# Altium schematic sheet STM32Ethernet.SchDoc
size A3
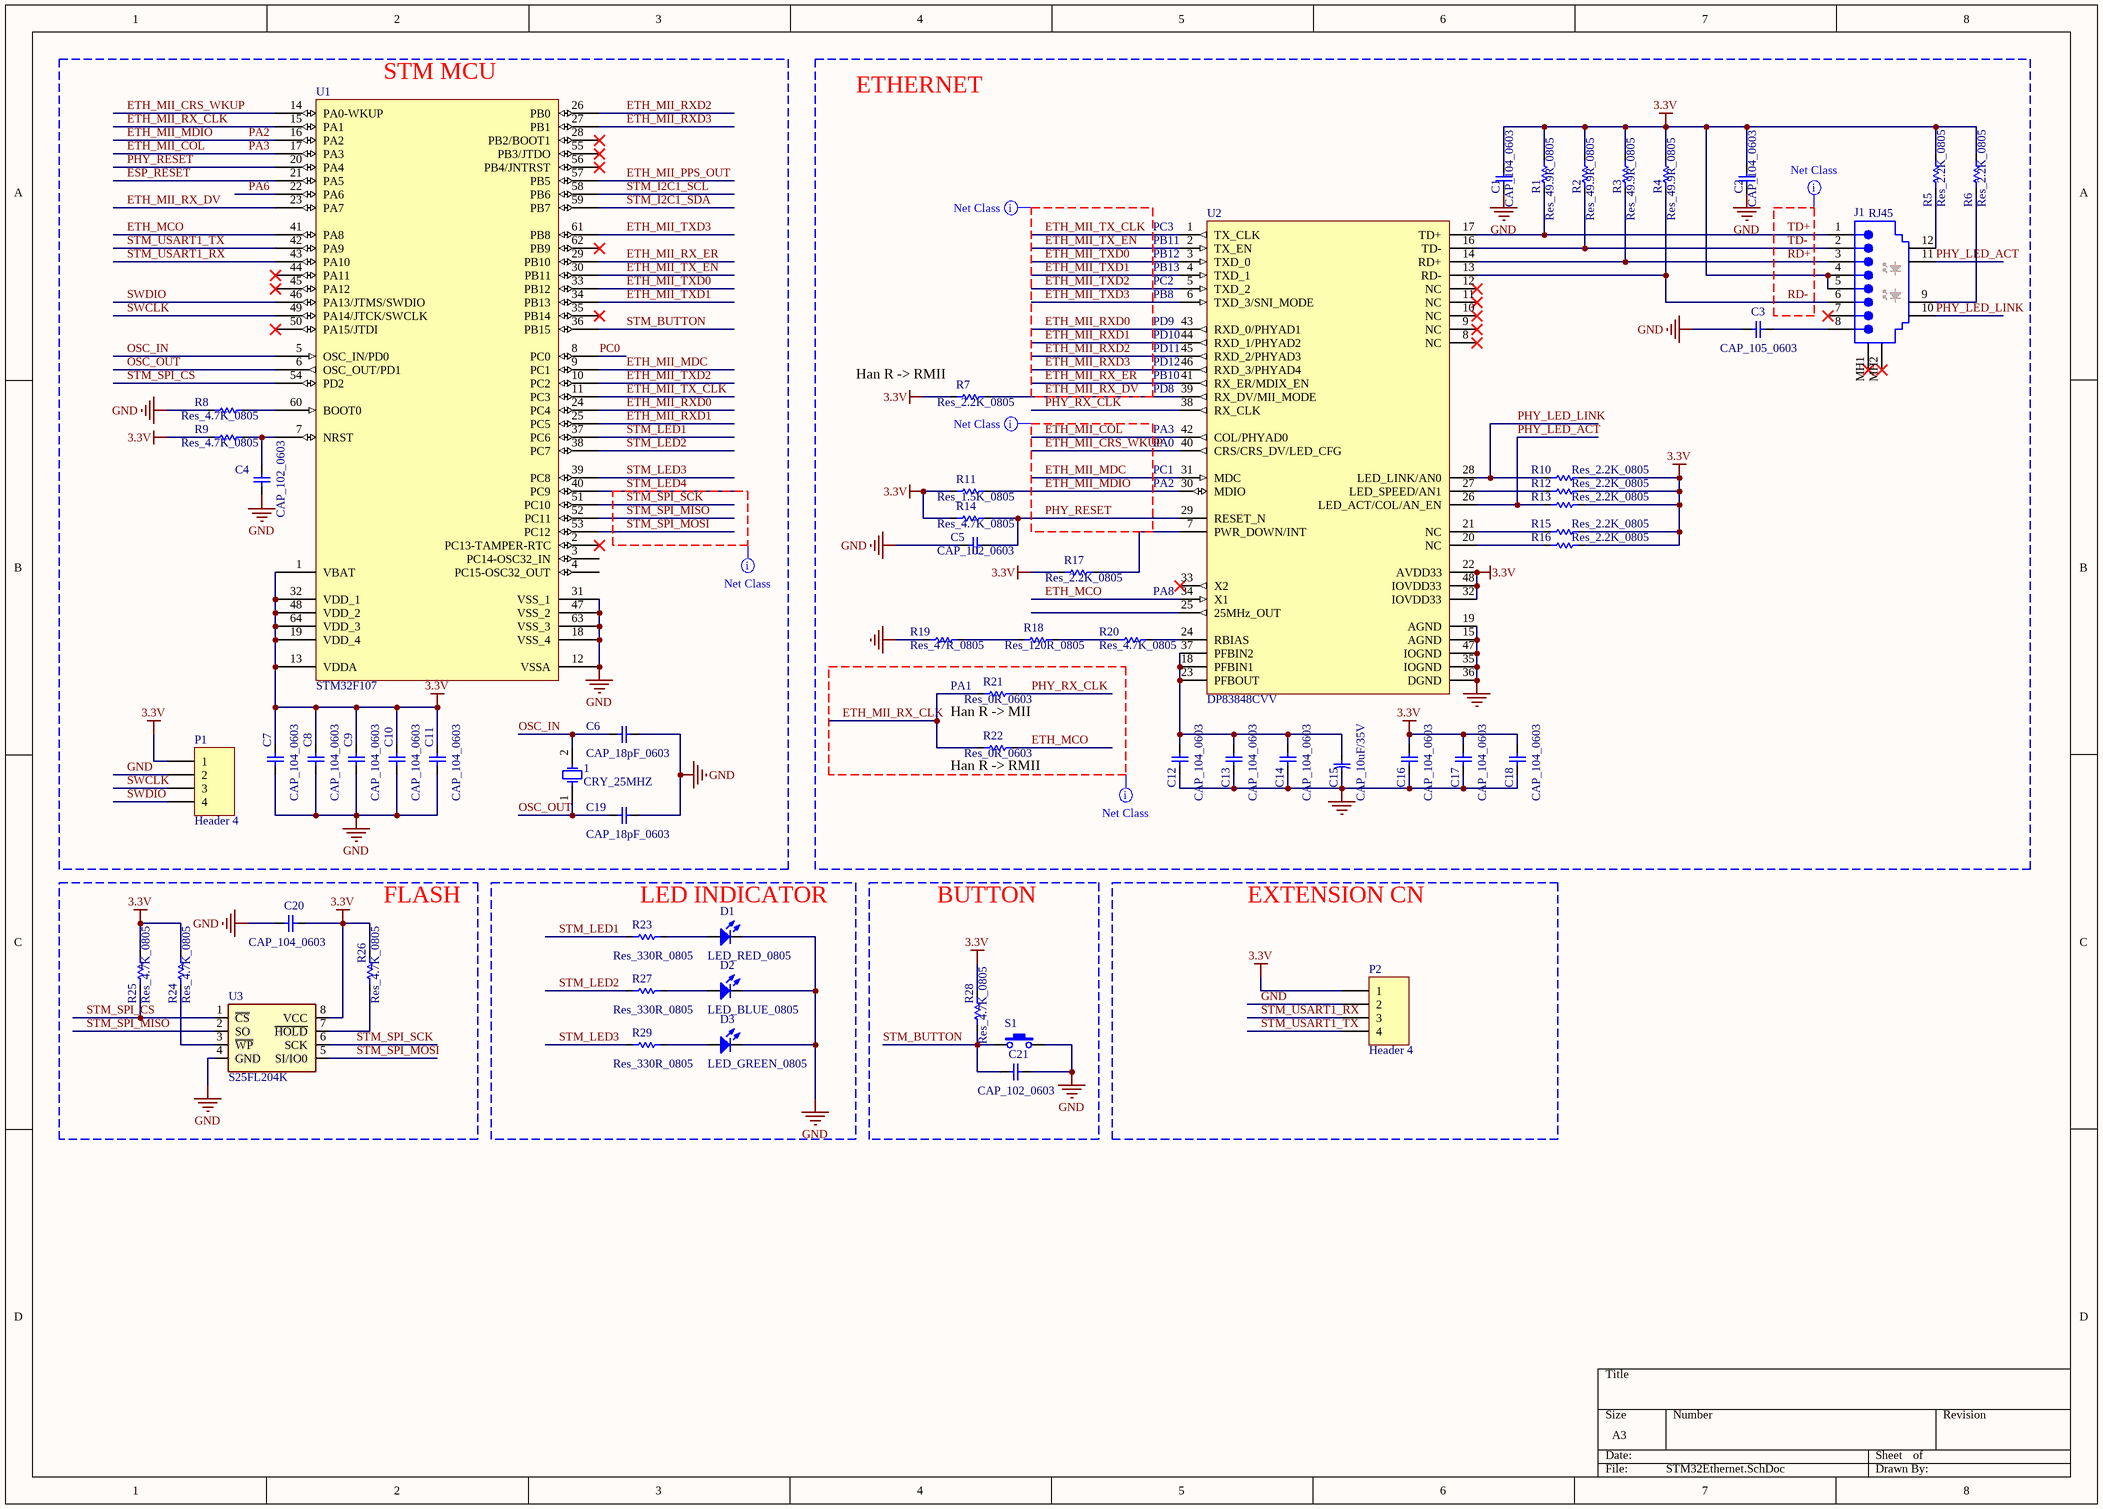
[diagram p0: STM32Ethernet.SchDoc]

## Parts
1  CRY_25MHZ  [cry]
C1  CAP_104_0603  [CAP_0805_TOP]
C2  CAP_104_0603  [CAP_0805_TOP]
C3  CAP_105_0603  [CAP_0805_TOP]
C4  CAP_102_0603  [CAP_0805_TOP]
C5  CAP_102_0603  [CAP_0805_TOP]
C6  CAP_18pF_0603  [CAP_0603_TOP]
C7  CAP_104_0603  [CAP_0805_TOP]
C8  CAP_104_0603  [CAP_0805_TOP]
C9  CAP_104_0603  [CAP_0805_TOP]
C10  CAP_104_0603  [CAP_0805_TOP]
C11  CAP_104_0603  [CAP_0805_TOP]
C12  CAP_104_0603  [CAP_0805_TOP]
C13  CAP_104_0603  [CAP_0805_TOP]
C14  CAP_104_0603  [CAP_0805_TOP]
C15  CAP_10uF/35V  [CAP_10uF/35V]
C16  CAP_104_0603  [CAP_0805_TOP]
C17  CAP_104_0603  [CAP_0805_TOP]
C18  CAP_104_0603  [CAP_0805_TOP]
C19  CAP_18pF_0603  [CAP_0603_TOP]
C20  CAP_104_0603  [CAP_0805_TOP]
C21  CAP_102_0603  [CAP_0805_TOP]
D1  LED_RED_0805  [LED 0805 TOP]
D2  LED_BLUE_0805  [LED 0805 TOP]
D3  LED_GREEN_0805  [LED 0805 TOP]
J1  RJ45  [CONNECTOR_RJ45_HR911102A]
P1  Header 4  [HDR1X4]
P2  Header 4  [HDR1X4]
R1  Res_49.9R_0805  [RES_0805_TOP]
R2  Res_49.9R_0805  [RES_0805_TOP]
R3  Res_49.9R_0805  [RES_0805_TOP]
R4  Res_49.9R_0805  [RES_0805_TOP]
R5  Res_2.2K_0805  [RES_0805_TOP]
R6  Res_2.2K_0805  [RES_0805_TOP]
R7  Res_2.2K_0805  [RES_0805_TOP]
R8  Res_4.7K_0805  [RES_0805_TOP]
R9  Res_4.7K_0805  [RES_0805_TOP]
R10  Res_2.2K_0805  [RES_0805_TOP]
R11  Res_1.5K_0805  [RES_0805_TOP]
R12  Res_2.2K_0805  [RES_0805_TOP]
R13  Res_2.2K_0805  [RES_0805_TOP]
R14  Res_4.7K_0805  [RES_0805_TOP]
R15  Res_2.2K_0805  [RES_0805_TOP]
R16  Res_2.2K_0805  [RES_0805_TOP]
R17  Res_2.2K_0805  [RES_0805_TOP]
R18  Res_120R_0805  [RES_0805_TOP]
R19  Res_47R_0805  [RES_0805_TOP]
R20  Res_4.7K_0805  [RES_0805_TOP]
R21  Res_0R_0603  [RES_0805_TOP]
R22  Res_0R_0603  [RES_0805_TOP]
R23  Res_330R_0805  [RES_0805_TOP]
R24  Res_4.7K_0805  [RES_0805_TOP]
R25  Res_4.7K_0805  [RES_0805_TOP]
R26  Res_4.7K_0805  [RES_0805_TOP]
R27  Res_330R_0805  [RES_0805_TOP]
R28  Res_4.7K_0805  [RES_0805_TOP]
R29  Res_330R_0805  [RES_0805_TOP]
S1  BUTTON 2P  [Nut nhan 2 chan  dung]  (value not drawn)
U1  STM32F107  [LQFP64_N]
U2  DP83848CVV  [LQFP48]
U3  S25FL204K  [SOIC_8]

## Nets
3.3V: C1.1 C2.1 C7.1 C8.1 C9.1 C10.1 C11.1 C16.2 C17.1 C18.2 C20.1 J1.4 J1.5 P1.1 P2.1 R1.1 R2.1 R3.1 R4.1 R5.1 R6.1 R7.2 R9.2 R10.1 R11.1 R12.1 R13.1 R14.1 R15.1 R16.1 R17.1 R24.1 R25.1 R26.1 R28.1 U1.1(VBAT) U1.13(VDDA) U1.19(VDD_4) U1.32(VDD_1) U1.48(VDD_2) U1.64(VDD_3) U2.22(AVDD33) U2.32(IOVDD33) U2.48(IOVDD33) U3.8(VCC)
GND: C1.2 C2.2 C3.1 C4.2 C5.1 C6.2 C7.2 C8.2 C9.2 C10.2 C11.2 C12.1 C13.1 C14.1 C15.2 C16.1 C17.2 C18.1 C19.2 C20.2 C21.2 D1.2(K) D2.2(K) D3.2(K) P1.2 P2.2 R8.2 R19.2 S1.2 U1.12(VSSA) U1.18(VSS_4) U1.31(VSS_1) U1.47(VSS_2) U1.63(VSS_3) U2.15(AGND) U2.19(AGND) U2.35(IOGND) U2.36(DGND) U2.47(IOGND) U3.4(GND)
ESP_RESET: U1.21(PA5)
ETH_MCO: R22.2 U1.41(PA8) U2.34(X1)
ETH_MII_COL: U1.17(PA3) U2.42(COL/PHYAD0)  [also labelled PA3]
ETH_MII_CRS_WKUP: U1.14(PA0-WKUP) U2.40(CRS/CRS_DV/LED_CFG)
ETH_MII_MDC: U1.9(PC1) U2.31(MDC)
ETH_MII_MDIO: R11.2 U1.16(PA2) U2.30(MDIO)  [also labelled PA2]
ETH_MII_PPS_OUT: U1.57(PB5)
ETH_MII_RX_CLK: R21.2 R22.1 U1.15(PA1)
ETH_MII_RX_DV: R7.1 U1.23(PA7) U2.39(RX_DV/MII_MODE)
ETH_MII_RX_ER: U1.29(PB10) U2.41(RX_ER/MDIX_EN)
ETH_MII_RXD0: U1.24(PC4) U2.43(RXD_0/PHYAD1)
ETH_MII_RXD1: U1.25(PC5) U2.44(RXD_1/PHYAD2)
ETH_MII_RXD2: U1.26(PB0) U2.45(RXD_2/PHYAD3)
ETH_MII_RXD3: U1.27(PB1) U2.46(RXD_3/PHYAD4)
ETH_MII_TX_CLK: U1.11(PC3) U2.1(TX_CLK)
ETH_MII_TX_EN: U1.30(PB11) U2.2(TX_EN)
ETH_MII_TXD0: U1.33(PB12) U2.3(TXD_0)
ETH_MII_TXD1: U1.34(PB13) U2.4(TXD_1)
ETH_MII_TXD2: U1.10(PC2) U2.5(TXD_2)
ETH_MII_TXD3: U1.61(PB8) U2.6(TXD_3/SNI_MODE)
OSC_IN: 1.2(OSC2) C6.1 U1.5(OSC_IN/PD0)
OSC_OUT: 1.1(OSC1) C19.1 U1.6(OSC_OUT/PD1)
PA6: U1.22(PA6)
PC0: U1.8(PC0)
PHY_LED_ACT: J1.11 R13.2 U2.26(LED_ACT/COL/AN_EN)
PHY_LED_LINK: J1.10 R10.2 U2.28(LED_LINK/AN0)
PHY_RESET: C5.2 R14.2 U1.20(PA4) U2.29(RESET_N)
PHY_RX_CLK: R21.1 U2.38(RX_CLK)
RD+: J1.3 R3.2 U2.14(RD+)
RD-: J1.6 R4.2 U2.13(RD-)
STM_BUTTON: C21.1 R28.2 S1.1 U1.36(PB15)
STM_I2C1_SCL: U1.58(PB6)
STM_I2C1_SDA: U1.59(PB7)
STM_LED1: R23.1 U1.37(PC6)
STM_LED2: R27.1 U1.38(PC7)
STM_LED3: R29.1 U1.39(PC8)
STM_LED4: U1.40(PC9)
STM_SPI_CS: R25.2 U1.54(PD2) U3.1(~{CS})
STM_SPI_MISO: U1.52(PC11) U3.2(SO)
STM_SPI_MOSI: U1.53(PC12) U3.5(SI/IO0)
STM_SPI_SCK: U1.51(PC10) U3.6(SCK)
STM_USART1_RX: P2.3 U1.43(PA10)
STM_USART1_TX: P2.4 U1.42(PA9)
SWCLK: P1.3 U1.49(PA14/JTCK/SWCLK)
SWDIO: P1.4 U1.46(PA13/JTMS/SWDIO)
TD+: J1.1 R1.2 U2.17(TD+)
TD-: J1.2 R2.2 U2.16(TD-)
NetC3_2: C3.2 J1.8
NetC4_1: C4.1 R9.1 U1.7(NRST)
NetC12_2: C12.2 C13.2 C14.2 C15.1 U2.18(PFBIN1) U2.23(PFBOUT) U2.37(PFBIN2)
NetD1_1: D1.1(A) R23.2
NetD2_1: D2.1(A) R27.2
NetD3_1: D3.1(A) R29.2
NetJ1_9: J1.9 R6.2
NetJ1_12: J1.12 R5.2
NetR8_1: R8.1 U1.60(BOOT0)
NetR12_2: R12.2 U2.27(LED_SPEED/AN1)
NetR15_2: R15.2 U2.21(NC)
NetR16_2: R16.2 U2.20(NC)
NetR17_2: R17.2 U2.7(PWR_DOWN/INT)
NetR18_1: R18.1 R19.1
NetR18_2: R18.2 R20.2
NetR20_1: R20.1 U2.24(RBIAS)
NetR24_2: R24.2 U3.3(~{WP})
NetR26_2: R26.2 U3.7(~{HOLD})

Not connected (* = marked no-connect by the designer): J1 7* MH1(Shield)* MH2(Shield)*; U1 2(PC13-TAMPER-RTC)* 3(PC14-OSC32_IN) 4(PC15-OSC32_OUT) 28(PB2/BOOT1)* 35(PB14)* 44(PA11)* 45(PA12)* 50(PA15/JTDI)* 55(PB3/JTDO)* 56(PB4/JNTRST)* 62(PB9)*; U2 8(NC)* 9(NC)* 10(NC)* 11(NC)* 12(NC)* 25(25MHz_OUT) 33(X2)*

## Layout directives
net class ETH_SIGN: 3.3V, ETH_MCO, ETH_MII_COL, ETH_MII_CRS_WKUP, ETH_MII_MDC, ETH_MII_MDIO, ETH_MII_RX_CLK, ETH_MII_RX_DV, ETH_MII_RX_ER, ETH_MII_RXD0, ETH_MII_RXD1, ETH_MII_RXD2, ETH_MII_RXD3, ETH_MII_TX_CLK, ETH_MII_TX_EN, ETH_MII_TXD0, ETH_MII_TXD1, ETH_MII_TXD2, ETH_MII_TXD3, GND, PHY_LED_ACT, PHY_LED_LINK, PHY_RESET, PHY_RX_CLK, RD+, RD-, TD+, TD-
net class ETH_CLK: 3.3V, ETH_MCO, ETH_MII_COL, ETH_MII_CRS_WKUP, ETH_MII_MDC, ETH_MII_MDIO, ETH_MII_RX_CLK, ETH_MII_RX_DV, ETH_MII_RX_ER, ETH_MII_RXD0, ETH_MII_RXD1, ETH_MII_RXD2, ETH_MII_RXD3, ETH_MII_TX_CLK, ETH_MII_TX_EN, ETH_MII_TXD0, ETH_MII_TXD1, ETH_MII_TXD2, ETH_MII_TXD3, GND, PHY_LED_ACT, PHY_LED_LINK, PHY_RESET, PHY_RX_CLK, RD+, RD-, TD+, TD-
net class PHY_OUT: 3.3V, ETH_MCO, ETH_MII_COL, ETH_MII_CRS_WKUP, ETH_MII_MDC, ETH_MII_MDIO, ETH_MII_RX_CLK, ETH_MII_RX_DV, ETH_MII_RX_ER, ETH_MII_RXD0, ETH_MII_RXD1, ETH_MII_RXD2, ETH_MII_RXD3, ETH_MII_TX_CLK, ETH_MII_TX_EN, ETH_MII_TXD0, ETH_MII_TXD1, ETH_MII_TXD2, ETH_MII_TXD3, GND, PHY_LED_ACT, PHY_LED_LINK, PHY_RESET, PHY_RX_CLK, RD+, RD-, TD+, TD-
net class SPI_DATA: 3.3V, ESP_RESET, ETH_MCO, ETH_MII_COL, ETH_MII_CRS_WKUP, ETH_MII_MDC, ETH_MII_MDIO, ETH_MII_PPS_OUT, ETH_MII_RX_CLK, ETH_MII_RX_DV, ETH_MII_RX_ER, ETH_MII_RXD0, ETH_MII_RXD1, ETH_MII_RXD2, ETH_MII_RXD3, ETH_MII_TX_CLK, ETH_MII_TX_EN, ETH_MII_TXD0, ETH_MII_TXD1, ETH_MII_TXD2, ETH_MII_TXD3, GND, OSC_IN, OSC_OUT, PA2, PA3, PA6, PC0, PHY_RESET, STM_BUTTON, STM_I2C1_SCL, STM_I2C1_SDA, STM_LED1, STM_LED2, STM_LED3, STM_LED4, STM_SPI_CS, STM_SPI_MISO, STM_SPI_MOSI, STM_SPI_SCK, STM_USART1_RX, STM_USART1_TX, SWCLK, SWDIO

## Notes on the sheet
- (near U1) STM MCU
- ETHERNET
- (near U2) PC3
- (near U2) PB11
- (near U2) PB12
- (near U2) PB13
- (near U2) PC2
- (near U2) PB8
- (near R7) Han R -> RMII
- (near U2) PD9
- (near U2) PD10
- (near U2) PD11
- (near U2) PD12
- (near U2) PB10
- (near U2) PD8
- (near U2) PA3
- (near U2) PA0
- (near U2) PC1
- (near U2) PA2
- PA8
- (near R21) PA1
- (near R21) Han R -> MII
- (near R22) Han R -> RMII
- (near R26) FLASH
- LED INDICATOR
- BUTTON
- EXTENSION CN

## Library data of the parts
1 = cry: Crystal Oscillator
C1-C14 C16-C21 = Cap 1206 BUT: Capacitor; Value: 104
C15 = CAP P: Value: CAP_220uF/6.3V
D1-D3 = LED 0805 TOP: Typical INFRARED GaAs LED
J1 = RJ45: RJ45 Connector, with Leds
P1 P2 = Header 4: Header, 4-Pin
R1-R29 = Res: Resistor
S1 = BUTTON 2P: Switch
U1 = STM32F103RBT6: STM32 ARM-based 32-bit MCU with 128 Kbytes Flash, 64-pin LQFP, Industrial Temperature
